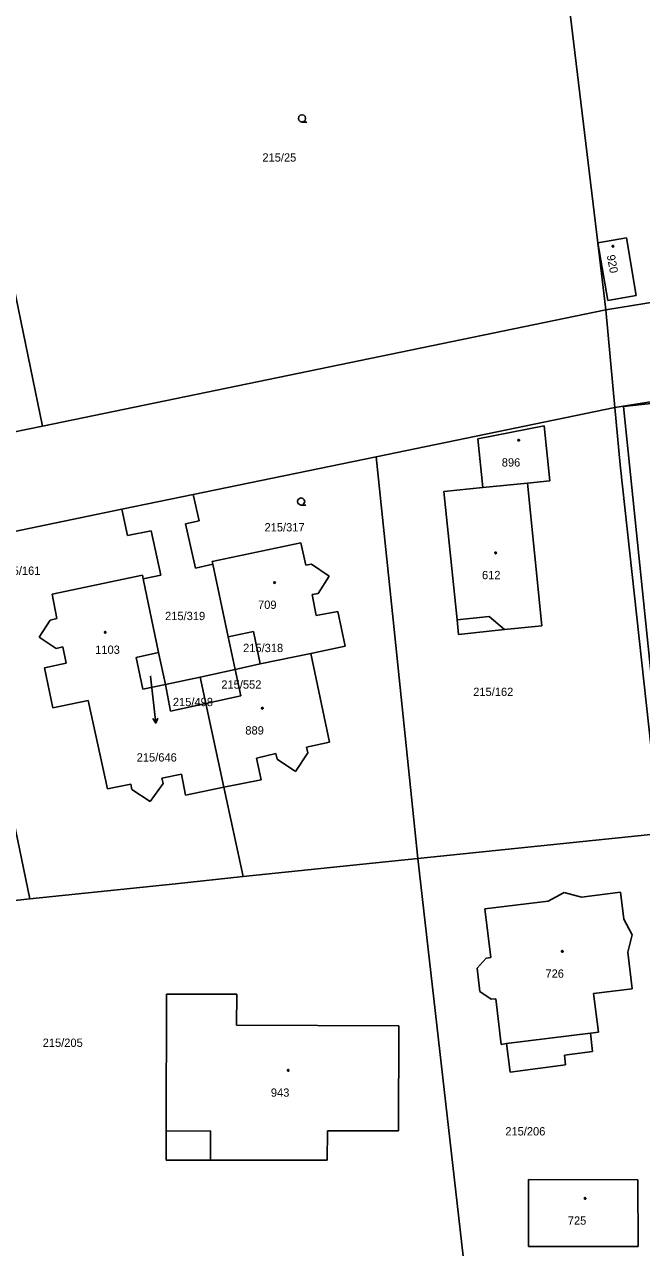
# Model space of a CAD drawing. Extents: x -757994 to -755874, y -1047691 to -1046119.
# Drawn here: x -757585.5 to -757522.2, y -1047587.6 to -1047462.2 of the extents above; entities that cross this region are included whole.
import ezdxf

# ---------------------------------------------------------------- set-up
doc = ezdxf.new("R2010")
doc.units = 0
doc.layers.add('katastrální mapa', color=7, linetype='Continuous')

msp = doc.modelspace()

# ---------------------------------------------------------------- linework, layer by layer
at = {"layer": 'katastrální mapa'}
for p, q in [((-757529.58, -1047461.08), (-757526.74, -1047484.57)), ((-757583.69, -1047503.34), (-757591.51, -1047465.44)), ((-757526.74, -1047484.57), (-757523.8, -1047484.06)), ((-757525.91, -1047491.41), (-757526.74, -1047484.57)), ((-757526.74, -1047484.57), (-757525.72, -1047490.46)), ((-757523.8, -1047484.06), (-757522.79, -1047489.95)), ((-757500.43, -1047487.34), (-757525.91, -1047491.41)), ((-757522.79, -1047489.95), (-757525.72, -1047490.46)), ((-757525.91, -1047491.41), (-757583.69, -1047503.34)), ((-757525.91, -1047491.41), (-757524.99, -1047501.43)), ((-757524.99, -1047501.43), (-757509.96, -1047499.03)), ((-757549.47, -1047506.48), (-757524.99, -1047501.43)), ((-757524.99, -1047501.43), (-757524.45, -1047507.31)), ((-757524.11, -1047501.34), (-757521.27, -1047501.02)), ((-757520.47, -1047536.52), (-757524.11, -1047501.34)), ((-757605.24, -1047507.79), (-757583.69, -1047503.34)), ((-757539.03, -1047504.65), (-757532.24, -1047503.31)), ((-757532.24, -1047503.31), (-757531.66, -1047508.95)), ((-757538.52, -1047509.65), (-757539.03, -1047504.65)), ((-757568.23, -1047510.36), (-757549.47, -1047506.48)), ((-757549.47, -1047506.48), (-757547.56, -1047524.83)), ((-757524.45, -1047507.31), (-757520.32, -1047545.09)), ((-757542.51, -1047510.06), (-757538.52, -1047509.65)), ((-757538.52, -1047509.65), (-757533.94, -1047509.18)), ((-757531.66, -1047508.95), (-757533.94, -1047509.18)), ((-757533.94, -1047509.18), (-757532.48, -1047523.81)), ((-757575.54, -1047511.86), (-757568.23, -1047510.36)), ((-757567.61, -1047513.05), (-757568.23, -1047510.36)), ((-757541.17, -1047523.19), (-757542.51, -1047510.06)), ((-757592.56, -1047515.38), (-757575.54, -1047511.86)), ((-757575.54, -1047511.86), (-757574.98, -1047514.57)), ((-757569.01, -1047513.36), (-757567.61, -1047513.05)), ((-757568, -1047517.89), (-757569.01, -1047513.36)), ((-757574.98, -1047514.57), (-757572.55, -1047514.07)), ((-757572.55, -1047514.07), (-757571.54, -1047518.63)), ((-757592.56, -1047515.38), (-757584.97, -1047551.81)), ((-757557.2, -1047515.31), (-757566.27, -1047517.21)), ((-757556.69, -1047517.61), (-757557.2, -1047515.31)), ((-757566.27, -1047517.21), (-757566.21, -1047517.51)), ((-757566.21, -1047517.51), (-757568, -1047517.89)), ((-757566.21, -1047517.51), (-757564.65, -1047524.94)), ((-757556.09, -1047517.5), (-757556.69, -1047517.61)), ((-757554.27, -1047518.73), (-757556.09, -1047517.5)), ((-757573.42, -1047518.63), (-757582.69, -1047520.56)), ((-757573.37, -1047519.01), (-757573.42, -1047518.63)), ((-757571.54, -1047518.63), (-757573.37, -1047519.01)), ((-757571.77, -1047526.56), (-757573.37, -1047519.01)), ((-757555.4, -1047520.49), (-757554.27, -1047518.73)), ((-757582.69, -1047520.56), (-757582.2, -1047523.07)), ((-757556.04, -1047520.61), (-757555.4, -1047520.49)), ((-757555.63, -1047522.77), (-757556.04, -1047520.61)), ((-757582.88, -1047523.22), (-757584.03, -1047524.97)), ((-757582.2, -1047523.07), (-757582.88, -1047523.22)), ((-757553.38, -1047522.34), (-757555.63, -1047522.77)), ((-757552.65, -1047525.9), (-757553.38, -1047522.34)), ((-757541.17, -1047523.19), (-757537.88, -1047522.86)), ((-757541.02, -1047524.7), (-757541.17, -1047523.19)), ((-757537.88, -1047522.86), (-757536.29, -1047524.2)), ((-757564.65, -1047524.94), (-757562.05, -1047524.4)), ((-757562.05, -1047524.4), (-757561.36, -1047527.73)), ((-757536.29, -1047524.2), (-757541.02, -1047524.7)), ((-757532.48, -1047523.81), (-757536.29, -1047524.2)), ((-757584.03, -1047524.97), (-757582.29, -1047526.13)), ((-757582.29, -1047526.13), (-757581.6, -1047525.98)), ((-757581.6, -1047525.98), (-757581.26, -1047527.66)), ((-757563.92, -1047528.3), (-757564.65, -1047524.94)), ((-757556.15, -1047526.64), (-757552.65, -1047525.9)), ((-757547.56, -1047524.83), (-757545.19, -1047547.67)), ((-757571.77, -1047526.56), (-757571.08, -1047529.83)), ((-757561.36, -1047527.73), (-757556.15, -1047526.64)), ((-757556.15, -1047526.64), (-757554.24, -1047535.75)), ((-757581.26, -1047527.66), (-757583.46, -1047528.12)), ((-757583.46, -1047528.12), (-757582.62, -1047532.24)), ((-757563.92, -1047528.3), (-757567.51, -1047529.07)), ((-757563.92, -1047528.3), (-757561.36, -1047527.73)), ((-757563.33, -1047531), (-757563.92, -1047528.3)), ((-757572.59, -1047528.97), (-757572.22, -1047532.3)), ((-757567.51, -1047529.07), (-757571.08, -1047529.83)), ((-757571.08, -1047529.83), (-757570.54, -1047532.56)), ((-757567.51, -1047529.07), (-757566.93, -1047531.78)), ((-757566.93, -1047531.78), (-757563.33, -1047531)), ((-757582.62, -1047532.24), (-757578.99, -1047531.48)), ((-757578.99, -1047531.48), (-757577.03, -1047540.52)), ((-757572.06, -1047533.79), (-757572.22, -1047532.3)), ((-757570.54, -1047532.56), (-757566.93, -1047531.78)), ((-757565.08, -1047540.37), (-757566.93, -1047531.78)), ((-757554.24, -1047535.75), (-757556.59, -1047536.25)), ((-757559.75, -1047536.89), (-757561.75, -1047537.4)), ((-757559.62, -1047537.5), (-757559.75, -1047536.89)), ((-757556.46, -1047536.85), (-757557.73, -1047538.75)), ((-757556.59, -1047536.25), (-757556.46, -1047536.85)), ((-757561.75, -1047537.4), (-757561.26, -1047539.59)), ((-757557.73, -1047538.75), (-757559.62, -1047537.5)), ((-757571.44, -1047539.44), (-757569.42, -1047539.02)), ((-757571.32, -1047539.99), (-757571.44, -1047539.44)), ((-757569.42, -1047539.02), (-757569.01, -1047541.16)), ((-757561.26, -1047539.59), (-757565.08, -1047540.37)), ((-757577.03, -1047540.52), (-757574.63, -1047540.04)), ((-757574.63, -1047540.04), (-757574.53, -1047540.59)), ((-757574.53, -1047540.59), (-757572.65, -1047541.81)), ((-757572.65, -1047541.81), (-757571.32, -1047539.99)), ((-757569.01, -1047541.16), (-757565.08, -1047540.37)), ((-757563.09, -1047549.53), (-757565.08, -1047540.37)), ((-757520.32, -1047545.09), (-757545.19, -1047547.67)), ((-757563.09, -1047549.53), (-757545.19, -1047547.67)), ((-757545.19, -1047547.67), (-757540.55, -1047588.43)), ((-757570.05, -1047550.26), (-757563.09, -1047549.53)), ((-757584.97, -1047551.81), (-757570.05, -1047550.26)), ((-757531.82, -1047552.03), (-757530.19, -1047551.15)), ((-757530.19, -1047551.15), (-757528.39, -1047551.62)), ((-757528.39, -1047551.62), (-757524.42, -1047551.13)), ((-757524.42, -1047551.13), (-757524.08, -1047553.9)), ((-757594.92, -1047552.84), (-757584.97, -1047551.81)), ((-757538.32, -1047552.82), (-757531.82, -1047552.03)), ((-757537.72, -1047557.81), (-757538.32, -1047552.82)), ((-757524.08, -1047553.9), (-757523.2, -1047555.51)), ((-757523.2, -1047555.51), (-757523.67, -1047557.28)), ((-757523.67, -1047557.28), (-757523.22, -1047561.02)), ((-757539.11, -1047558.92), (-757538.17, -1047557.87)), ((-757538.17, -1047557.87), (-757537.72, -1047557.81)), ((-757538.84, -1047561.29), (-757539.11, -1047558.92)), ((-757523.22, -1047561.02), (-757527.18, -1047561.52)), ((-757571, -1047575.61), (-757570.97, -1047561.56)), ((-757570.97, -1047561.56), (-757563.76, -1047561.57)), ((-757563.76, -1047561.57), (-757563.77, -1047564.77)), ((-757537.68, -1047562.1), (-757538.84, -1047561.29)), ((-757537.2, -1047562.04), (-757537.68, -1047562.1)), ((-757536.64, -1047566.72), (-757537.2, -1047562.04)), ((-757527.18, -1047561.52), (-757526.67, -1047565.48)), ((-757563.77, -1047564.77), (-757547.15, -1047564.81)), ((-757547.15, -1047564.81), (-757547.17, -1047575.59)), ((-757536.09, -1047566.65), (-757527.49, -1047565.58)), ((-757526.67, -1047565.48), (-757527.49, -1047565.58)), ((-757527.49, -1047565.58), (-757527.26, -1047567.47)), ((-757536.09, -1047566.65), (-757536.64, -1047566.72)), ((-757535.73, -1047569.56), (-757536.09, -1047566.65)), ((-757527.26, -1047567.47), (-757530.16, -1047567.83)), ((-757530.16, -1047567.83), (-757530.04, -1047568.83)), ((-757530.04, -1047568.83), (-757535.73, -1047569.56)), ((-757571.01, -1047578.61), (-757571, -1047575.61)), ((-757571, -1047575.61), (-757566.45, -1047575.6)), ((-757566.45, -1047575.6), (-757566.46, -1047578.61)), ((-757554.47, -1047575.6), (-757554.48, -1047578.6)), ((-757547.17, -1047575.59), (-757554.47, -1047575.6)), ((-757566.46, -1047578.61), (-757571.01, -1047578.61)), ((-757554.48, -1047578.6), (-757566.46, -1047578.61)), ((-757533.84, -1047587.43), (-757533.83, -1047580.59)), ((-757533.83, -1047580.59), (-757522.63, -1047580.62)), ((-757522.63, -1047580.62), (-757522.61, -1047587.44)), ((-757522.61, -1047587.44), (-757533.84, -1047587.43))]:
    msp.add_line(p, q, dxfattribs=at)
for points in [[(-757557.06, -1047472.17), (-757557.25, -1047472.12), (-757557.39, -1047471.99), (-757557.44, -1047471.8), (-757557.39, -1047471.62), (-757557.25, -1047471.48), (-757557.07, -1047471.43), (-757556.88, -1047471.48), (-757556.75, -1047471.62), (-757556.7, -1047471.81), (-757556.75, -1047472), (-757556.88, -1047472.13), (-757557.07, -1047472.18), (-757556.57, -1047472.18)], [(-757557.15, -1047511.44), (-757557.34, -1047511.39), (-757557.48, -1047511.25), (-757557.53, -1047511.07), (-757557.48, -1047510.89), (-757557.34, -1047510.75), (-757557.16, -1047510.7), (-757556.97, -1047510.75), (-757556.84, -1047510.89), (-757556.79, -1047511.08), (-757556.84, -1047511.26), (-757556.97, -1047511.4), (-757557.16, -1047511.45), (-757556.66, -1047511.45)], [(-757571.08, -1047529.83), (-757573.38, -1047530.31), (-757574.06, -1047527.05), (-757571.77, -1047526.56)], [(-757571.86, -1047533.27), (-757572.06, -1047533.79), (-757572.36, -1047533.32)]]:
    msp.add_lwpolyline(points, dxfattribs=at)
for points in [[(-757525.19, -1047484.83), (-757525.14, -1047484.84), (-757525.11, -1047484.88), (-757525.1, -1047484.91), (-757525.11, -1047484.96), (-757525.16, -1047484.99), (-757525.19, -1047485), (-757525.23, -1047484.98), (-757525.26, -1047484.95), (-757525.27, -1047484.91), (-757525.26, -1047484.87), (-757525.22, -1047484.83)], [(-757534.85, -1047504.71), (-757534.8, -1047504.72), (-757534.77, -1047504.76), (-757534.76, -1047504.79), (-757534.77, -1047504.84), (-757534.82, -1047504.87), (-757534.85, -1047504.88), (-757534.9, -1047504.86), (-757534.93, -1047504.83), (-757534.94, -1047504.79), (-757534.93, -1047504.75), (-757534.89, -1047504.71)], [(-757537.21, -1047516.25), (-757537.16, -1047516.26), (-757537.14, -1047516.31), (-757537.12, -1047516.34), (-757537.14, -1047516.39), (-757537.18, -1047516.42), (-757537.21, -1047516.43), (-757537.25, -1047516.41), (-757537.28, -1047516.38), (-757537.29, -1047516.34), (-757537.28, -1047516.29), (-757537.24, -1047516.26)], [(-757559.89, -1047519.29), (-757559.84, -1047519.3), (-757559.82, -1047519.35), (-757559.8, -1047519.38), (-757559.82, -1047519.43), (-757559.85, -1047519.46), (-757559.89, -1047519.47), (-757559.94, -1047519.45), (-757559.97, -1047519.42), (-757559.98, -1047519.38), (-757559.97, -1047519.34), (-757559.93, -1047519.3)], [(-757577.25, -1047524.41), (-757577.2, -1047524.42), (-757577.18, -1047524.46), (-757577.17, -1047524.49), (-757577.18, -1047524.53), (-757577.22, -1047524.57), (-757577.25, -1047524.58), (-757577.29, -1047524.56), (-757577.33, -1047524.53), (-757577.34, -1047524.49), (-757577.33, -1047524.45), (-757577.28, -1047524.41)], [(-757561.13, -1047532.18), (-757561.08, -1047532.19), (-757561.05, -1047532.23), (-757561.04, -1047532.26), (-757561.05, -1047532.3), (-757561.1, -1047532.34), (-757561.13, -1047532.35), (-757561.18, -1047532.33), (-757561.21, -1047532.3), (-757561.22, -1047532.26), (-757561.21, -1047532.22), (-757561.17, -1047532.18)], [(-757530.37, -1047557.11), (-757530.32, -1047557.12), (-757530.29, -1047557.16), (-757530.28, -1047557.19), (-757530.29, -1047557.23), (-757530.34, -1047557.27), (-757530.37, -1047557.27), (-757530.42, -1047557.26), (-757530.45, -1047557.23), (-757530.46, -1047557.19), (-757530.45, -1047557.15), (-757530.41, -1047557.11)], [(-757558.48, -1047569.3), (-757558.43, -1047569.32), (-757558.41, -1047569.36), (-757558.4, -1047569.39), (-757558.41, -1047569.44), (-757558.45, -1047569.47), (-757558.48, -1047569.48), (-757558.52, -1047569.46), (-757558.55, -1047569.43), (-757558.57, -1047569.39), (-757558.55, -1047569.35), (-757558.51, -1047569.31)], [(-757528.04, -1047582.43), (-757527.99, -1047582.44), (-757527.97, -1047582.48), (-757527.96, -1047582.51), (-757527.97, -1047582.55), (-757528.01, -1047582.59), (-757528.04, -1047582.6), (-757528.09, -1047582.58), (-757528.11, -1047582.55), (-757528.12, -1047582.51), (-757528.11, -1047582.47), (-757528.08, -1047582.43)]]:
    msp.add_lwpolyline(points, close=True, dxfattribs=at)

# ---------------------------------------------------------------- texts
for s, height, p in [('215/25', 0.85, (-757561.13, -1047476.23)), ('896', 0.85, (-757536.58, -1047507.49)), ('215/317', 0.85, (-757560.91, -1047514.14)), ('215/161', 0.85, (-757588, -1047518.59)), ('612', 0.85, (-757538.61, -1047519.04)), ('709', 0.85, (-757561.58, -1047522.08)), ('215/319', 0.85, (-757571.11, -1047523.23)), ('1103', 0.85, (-757578.28, -1047526.69)), ('215/318', 0.85, (-757563.11, -1047526.51)), ('215/646', 0.05, (-757572.72, -1047528.97)), ('215/552', 0.85, (-757565.34, -1047530.26)), ('215/162', 0.85, (-757539.51, -1047531.01)), ('215/498', 0.85, (-757570.31, -1047532.05)), ('889', 0.85, (-757562.88, -1047534.96)), ('215/646', 0.85, (-757574.02, -1047537.73)), ('726', 0.85, (-757532.1, -1047559.89)), ('215/205', 0.85, (-757583.66, -1047566.98)), ('943', 0.85, (-757560.26, -1047572.09)), ('215/206', 0.85, (-757536.22, -1047576.06)), ('725', 0.85, (-757529.81, -1047585.21))]:
    msp.add_text(s, height=height, dxfattribs=at).set_placement(p)
msp.add_text('920', height=0.85, rotation=280.692, dxfattribs=at).set_placement((-757525.82, -1047485.86))

doc.saveas('drawing.dxf')
